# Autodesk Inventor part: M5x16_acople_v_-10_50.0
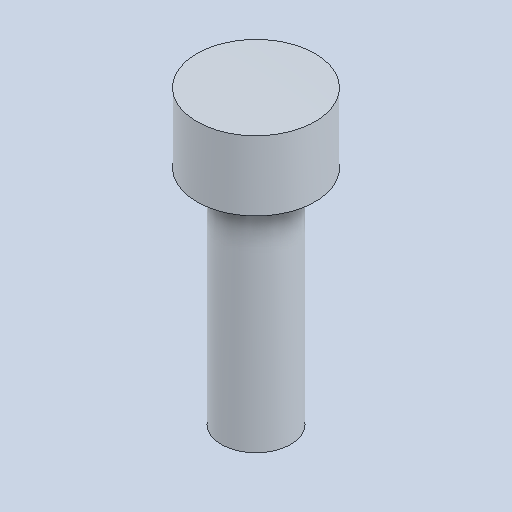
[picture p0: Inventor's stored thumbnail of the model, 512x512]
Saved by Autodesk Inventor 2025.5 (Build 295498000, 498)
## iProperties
Created: 2026-10
Part Number: M5x16_acople_v_-10_50.0
Material: Genérico
Document SubType Name: Modeling
Designer: Luis M
Density: 1 g/cm^3
Appearance: Valor por defecto
Author: Luis M
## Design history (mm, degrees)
feature "Base1"
node "Sólido1"
